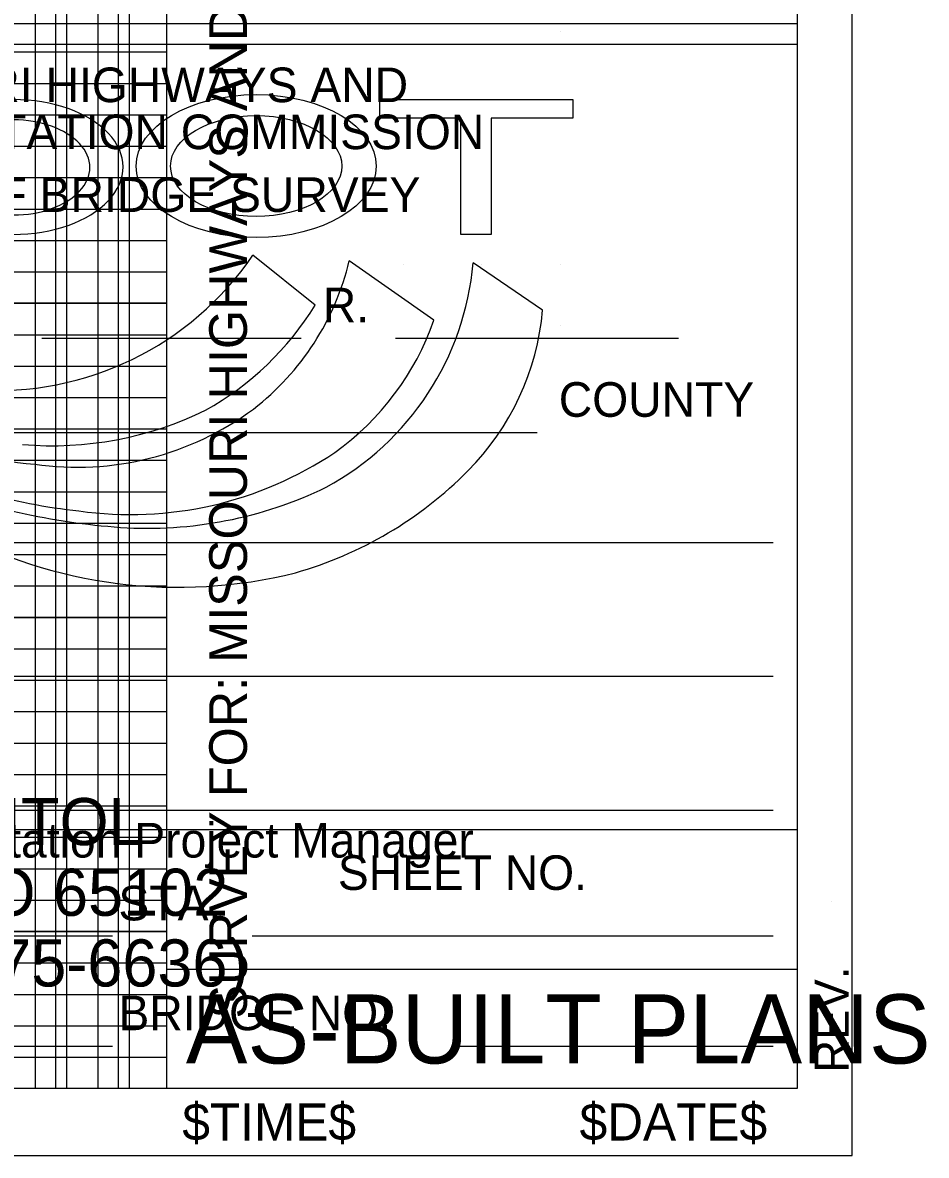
# Model space of a CAD drawing. Extents: x -0.2 to 31.7, y -0.2 to 20.6.
# Drawn here: x 28.784 to 31.661, y -0.212 to 3.393 of the extents above; entities that cross this region are included whole.
import ezdxf

# ---------------------------------------------------------------- set-up
doc = ezdxf.new("R2010")
doc.units = 0
for name, color, linetype in [('Border-Border', 7, 'Continuous'), ('Border-Bridge survey title block', 7, 'Continuous'), ('Border-Construction Final Plans Stamp', 7, 'Continuous'), ('Border-Cookie Cutter Template', 7, 'Continuous'), ('Border-Date stamp', 7, 'Continuous'), ('Border-English xsection major lines', 7, 'Continuous'), ('Border-English xsection minor lines', 7, 'Continuous'), ('Border-Full profile major grid lines', 7, 'Continuous'), ('Border-Geopak xsection major grid lines', 7, 'Continuous'), ('Border-Geopak xsection minor lines 1', 7, 'Continuous'), ('Border-Geopak xsection minor lines 2', 7, 'Continuous'), ('Border-Plan-profile major grid lines', 7, 'Continuous'), ('Border-Plotting block', 7, 'Continuous'), ('Border-Revision note', 7, 'Continuous'), ('Border-Time stamp', 7, 'Continuous'), ('Border-Title block - A-size Landscape Electronic Seal', 7, 'Continuous'), ('Border-Title block - Final Plans Consultant Manual Seal', 7, 'Continuous'), ('Border-Title block - Final Plans Electronic Seal', 7, 'Continuous'), ('Border-Title block - Location Survey Electronic Seal', 7, 'Continuous'), ('Border-Title block - Standard Plans Electronic Seal', 7, 'Continuous'), ('Border-Xsection shape', 7, 'Continuous'), ('Common-Sheet info', 7, 'Continuous')]:
    doc.layers.add(name, color=color, linetype=linetype)

msp = doc.modelspace()

# ---------------------------------------------------------------- linework, layer by layer
at = {"layer": 'Border-Border'}
for p, q in [((31.25, 20.375), (31.25, 0)), ((31.25, 0), (0, 0)), ((31.4249, -0.2125), (31.4249, -0.2125))]:
    msp.add_line(p, q, dxfattribs=at)
at = {"layer": 'Border-Bridge survey title block'}
for p, q in [((26.7664, 3.3906), (31.2499, 3.3906)), ((28.845, 2.389), (29.6704, 2.389)), ((29.9715, 2.389), (30.872, 2.389)), ((28.2689, 2.0882), (30.4216, 2.0882)), ((28.5253, 1.7386), (31.1728, 1.7386)), ((28.2056, 1.3126), (31.1728, 1.3126)), ((28.0914, 0.8866), (31.1728, 0.8866)), ((27.9544, 0.4866), (29.0704, 0.4866)), ((29.5148, 0.4866), (31.1728, 0.4866)), ((27.7414, 0.1354), (29.0704, 0.1354)), ((30.1618, 0.1354), (31.1728, 0.1354))]:
    msp.add_line(p, q, dxfattribs=at)
at = {"layer": 'Border-Construction Final Plans Stamp'}
msp.add_line((29.2421, 0.38), (31.2499, 0.38), dxfattribs=at)
at = {"layer": 'Border-Cookie Cutter Template'}
for p, q in [((29.2421, 20.375), (29.2421, 0)), ((31.2499, 20.375), (31.2499, 0)), ((31.2499, 0), (0, 0))]:
    msp.add_line(p, q, dxfattribs=at)
at = {"layer": 'Border-English xsection major lines'}
for p, q in [((0, 3), (29.2421, 3)), ((0, 2), (29.2421, 2)), ((0, 1), (29.2421, 1))]:
    msp.add_line(p, q, dxfattribs=at)
at = {"layer": 'Border-English xsection minor lines'}
for p, q in [((28.8899, 0), (28.8899, 20.375)), ((29.0899, 0), (29.0899, 20.375)), ((0, 3.2), (29.2421, 3.2)), ((0, 2.8), (29.2421, 2.8)), ((0, 2.6), (29.2421, 2.6)), ((0, 2.4), (29.2421, 2.4)), ((0, 2.2), (29.2421, 2.2)), ((0, 1.8), (29.2421, 1.8)), ((0, 1.6), (29.2421, 1.6)), ((0, 1.4), (29.2421, 1.4)), ((0, 1.2), (29.2421, 1.2)), ((0, 0.8), (29.2421, 0.8)), ((0, 0.6), (29.2421, 0.6)), ((0, 0.4), (29.2421, 0.4)), ((0, 0.2), (29.2421, 0.2))]:
    msp.add_line(p, q, dxfattribs=at)
at = {"layer": 'Border-Full profile major grid lines'}
for p, q in [((29.2421, 2.5), (0, 2.5)), ((29.2421, 1.5), (0, 1.5)), ((29.2421, 0.5), (0, 0.5))]:
    msp.add_line(p, q, dxfattribs=at)
at = {"layer": 'Border-Geopak xsection major grid lines'}
for p, q in [((0, 3), (29.2421, 3)), ((0, 2), (29.2421, 2)), ((0, 1), (29.2421, 1))]:
    msp.add_line(p, q, dxfattribs=at)
at = {"layer": 'Border-Geopak xsection minor lines 1'}
for p, q in [((28.9249, 0), (28.9249, 20.375)), ((29.1249, 0), (29.1249, 20.375)), ((0, 3.3), (29.2421, 3.3)), ((0, 3.1), (29.2421, 3.1)), ((0, 2.9), (29.2421, 2.9)), ((0, 2.7), (29.2421, 2.7)), ((0, 2.5), (29.2421, 2.5)), ((0, 2.3), (29.2421, 2.3)), ((0, 2.1), (29.2421, 2.1)), ((0, 1.9), (29.2421, 1.9)), ((0, 1.7), (29.2421, 1.7)), ((0, 1.5), (29.2421, 1.5)), ((0, 1.3), (29.2421, 1.3)), ((0, 1.1), (29.2421, 1.1)), ((0, 0.9), (29.2421, 0.9)), ((0, 0.7), (29.2421, 0.7)), ((0, 0.5), (29.2421, 0.5)), ((0, 0.3), (29.2421, 0.3)), ((0, 0.1), (29.2421, 0.1))]:
    msp.add_line(p, q, dxfattribs=at)
at = {"layer": 'Border-Geopak xsection minor lines 2'}
for p, q in [((28.8249, 0), (28.8249, 20.375)), ((29.0249, 0), (29.0249, 20.375)), ((0, 3.2), (29.2421, 3.2)), ((0, 2.8), (29.2421, 2.8)), ((0, 2.6), (29.2421, 2.6)), ((0, 2.4), (29.2421, 2.4)), ((0, 2.2), (29.2421, 2.2)), ((0, 1.8), (29.2421, 1.8)), ((0, 1.6), (29.2421, 1.6)), ((0, 1.4), (29.2421, 1.4)), ((0, 1.2), (29.2421, 1.2)), ((0, 0.8), (29.2421, 0.8)), ((0, 0.6), (29.2421, 0.6)), ((0, 0.4), (29.2421, 0.4)), ((0, 0.2), (29.2421, 0.2))]:
    msp.add_line(p, q, dxfattribs=at)
at = {"layer": 'Border-Plan-profile major grid lines'}
for p, q in [((29.2421, 2.5), (0, 2.5)), ((29.2421, 1.5), (0, 1.5)), ((29.2421, 0.5), (0, 0.5))]:
    msp.add_line(p, q, dxfattribs=at)
at = {"layer": 'Border-Plotting block'}
msp.add_lwpolyline([(-0.175, -0.2125), (31.4249, -0.2125), (31.4249, 20.5875), (-0.175, 20.5875)], close=True, dxfattribs=at)
at = {"layer": 'Border-Revision note'}
msp.add_line((31.3597, 0.5967), (31.3597, 0.5967), dxfattribs=at)
at = {"layer": 'Border-Title block - A-size Landscape Electronic Seal'}
for p, q in [((29.7157, 2.4943), (29.5176, 2.6534)), ((30.0933, 2.4462), (29.8242, 2.6347)), ((30.4395, 2.4776), (30.2183, 2.6283))]:
    msp.add_line(p, q, dxfattribs=at)
msp.add_lwpolyline([(29.9217, 3.1485), (30.5352, 3.1485), (30.5352, 3.0888), (30.2761, 3.0888), (30.2761, 2.7194), (30.1789, 2.7194), (30.1789, 3.0888), (29.9217, 3.0888)], close=True, dxfattribs=at)
for centre, radius, start, end in [((28.7015, 3.2095), 0.9875, 266.1033, 325.7272), ((28.7015, 3.2095), 0.9875, 325.7274, 325.7276), ((28.9983, 2.8346), 0.8497, 307.8205, 346.3964), ((29.3188, 2.7072), 0.903, 298.5725, 354.9889), ((28.8971, 2.9975), 0.9608, 299.2666, 328.4191), ((29.6134, 2.5513), 0.8294, 315.1693, 354.902), ((29.2754, 2.7303), 0.8658, 305.4806, 340.8474), ((29.0337, 4.1035), 2.1265, 240.8019, 264.3058), ((28.8777, 3.1629), 1.1164, 265.2048, 295.9837), ((28.9566, 2.9249), 0.9469, 261.8718, 306.464), ((29.1275, 2.9948), 1.1675, 261.9272, 303.854), ((29.1645, 3.6951), 1.867, 244.3097, 263.8237), ((29.311, 2.8469), 1.2523, 285.8221, 315.3322), ((29.2595, 4.0405), 2.2598, 249.2778, 265.8465), ((29.1813, 3.0917), 1.3079, 266.2526, 295.8037), ((29.2792, 3.1295), 1.5336, 241.4589, 284.0852)]:
    msp.add_arc(centre, radius, start, end, dxfattribs=at)
for centre, major_axis, ratio in [((28.7545, 2.9339), (-0.3494, 0), 0.614143), ((28.7545, 2.9324), (-0.2438, 0), 0.62091)]:
    msp.add_ellipse(centre, major_axis=major_axis, ratio=ratio, start_param=1.570796, end_param=4.712389, dxfattribs=at)
for centre, major_axis, ratio in [((29.5278, 2.9367), (0.382, 0), 0.595517), ((29.5277, 2.9367), (-0.2725, 0), 0.589579)]:
    msp.add_ellipse(centre, major_axis=major_axis, ratio=ratio, dxfattribs=at)
at = {"layer": 'Border-Title block - Final Plans Consultant Manual Seal'}
msp.add_line((29.2421, 20.375), (29.2421, 0), dxfattribs=at)
at = {"layer": 'Border-Title block - Final Plans Electronic Seal'}
for p, q in [((29.2421, 20.375), (29.2421, 0)), ((30.2461, 2.6237), (30.2461, 2.6237))]:
    msp.add_line(p, q, dxfattribs=at)
at = {"layer": 'Border-Title block - Location Survey Electronic Seal'}
msp.add_line((29.2421, 20.375), (29.2421, 0), dxfattribs=at)
at = {"layer": 'Border-Title block - Standard Plans Electronic Seal'}
for p, q in [((23.2499, 3.325), (31.25, 3.325)), ((23.2499, 0.825), (31.25, 0.825)), ((29.2421, 0.825), (29.2421, 0))]:
    msp.add_line(p, q, dxfattribs=at)
at = {"layer": 'Border-Xsection shape'}
msp.add_lwpolyline([(29.2421, 0), (0, 0), (0, 20.375), (29.2421, 20.375)], close=True, dxfattribs=at)
at = {"layer": 'Common-Sheet info'}
for p, q in [((30.4961, 3.3652), (30.4961, 3.3652)), ((29.9961, 2.6237), (29.9961, 2.6237)), ((30.2461, 2.6237), (30.2461, 2.6237)), ((30.4961, 2.6242), (30.4961, 2.6242)), ((30.4961, 2.4299), (30.4961, 2.4299))]:
    msp.add_line(p, q, dxfattribs=at)

# ---------------------------------------------------------------- texts
at = {"layer": 'Border-Bridge survey title block'}
for s, height, p in [('MISSOURI HIGHWAYS AND', 0.110166, (28.0878, 3.1402)), ('TRANSPORTATION COMMISSION', 0.110192, (27.8878, 2.9906)), ('REPORT OF BRIDGE SURVEY', 0.110192, (27.9381, 2.7906)), ('R.', 0.11019, (29.7397, 2.4393)), ('COUNTY', 0.11019, (30.4909, 2.1386)), ('Transportation Project Manager', 0.110166, (28.1488, 0.7355)), ('STA.', 0.11019, (29.0893, 0.5354)), ('BRIDGE NO.', 0.11019, (29.0893, 0.1858))]:
    msp.add_text(s, height=height, dxfattribs=at).set_placement(p)
at = {"layer": 'Border-Construction Final Plans Stamp'}
msp.add_text('AS-BUILT PLANS', height=0.219994, dxfattribs=at).set_placement((29.3038, 0.08))
at = {"layer": 'Border-Date stamp'}
msp.add_text('$DATE$', height=0.11811, dxfattribs=at).set_placement((30.5571, -0.1653))
at = {"layer": 'Border-Revision note'}
msp.add_text('REV.', height=0.10827, rotation=90, dxfattribs=at).set_placement((31.4138, 0.0505))
at = {"layer": 'Border-Time stamp'}
msp.add_text('$TIME$', height=0.11811, dxfattribs=at).set_placement((29.2927, -0.1653))
at = {"layer": 'Border-Title block - A-size Landscape Electronic Seal'}
for s, p in [('105 WEST CAPITOL', (27.2857, 0.775)), ('JEFFERSON CITY, MO 65102', (26.6857, 0.55)), ('1-888-ASK-MODOT (1-888-275-6636)', (26.0919, 0.325))]:
    msp.add_text(s, height=0.15, dxfattribs=at).set_placement(p)
at = {"layer": 'Border-Title block - Location Survey Electronic Seal'}
msp.add_text('SURVEY FOR: MISSOURI HIGHWAYS AND TRANSPORTATION COMMISSION', height=0.12, rotation=90, dxfattribs=at).set_placement((29.4984, 0.2231))
at = {"layer": 'Border-Title block - Standard Plans Electronic Seal'}
msp.add_text('SHEET NO.', height=0.11, dxfattribs=at).set_placement((29.7878, 0.6325))

doc.saveas('drawing.dxf')
